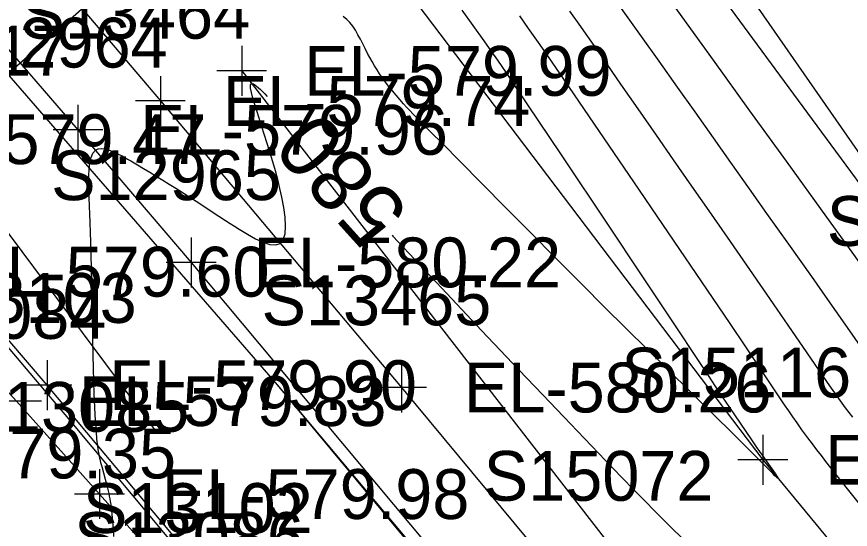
# Model space of a CAD drawing. Extents: x 1729869 to 1735532, y 648588 to 653771.
# Drawn here: x 1731311 to 1731377.9, y 651929.3 to 651970.4 of the extents above; entities that cross this region are included whole.
import ezdxf

# ---------------------------------------------------------------- set-up
doc = ezdxf.new("R2010")
doc.units = 0
for name, color, linetype in [('SURVEY - CENTERLINE - Preliminary', 7, 'Continuous'), ('SURVEY - CENTERLINE - Preliminary Text', 7, 'Continuous'), ('SURVEY - CONTOURS - Index with Text', 7, 'Continuous'), ('SURVEY - CONTOURS - Intermediate with optional Text', 7, 'Continuous'), ('SURVEY - DRAINAGE - Area Shapes', 7, 'Continuous'), ('SURVEY - DRAINAGE - Area Shapes Text', 7, 'Continuous'), ('SURVEY - DRAINAGE - Storm Sewer', 7, 'Continuous'), ('SURVEY - DTM - Breaklines', 7, 'Continuous'), ('SURVEY - DTM - Breaklines - Points - Elevations', 7, 'Continuous'), ('SURVEY - DTM - Breaklines - Points - Locators', 7, 'Continuous'), ('SURVEY - DTM - Breaklines - Points - Numbers', 7, 'Continuous'), ('SURVEY - TRANSPORTATION - Features', 7, 'Continuous'), ('SURVEY - TRANSPORTATION - Features - Points - Elevations', 7, 'Continuous'), ('SURVEY - TRANSPORTATION - Features - Points - Locators', 7, 'Continuous'), ('SURVEY - TRANSPORTATION - Features - Points - Numbers', 7, 'Continuous'), ('SURVEY - TRANSPORTATION - Roads', 7, 'Continuous'), ('SURVEY - TRANSPORTATION - Roads - Points - Elevations', 7, 'Continuous'), ('SURVEY - TRANSPORTATION - Roads - Points - Locators', 7, 'Continuous'), ('SURVEY - TRANSPORTATION - Roads - Points - Numbers', 7, 'Continuous')]:
    doc.layers.add(name, color=color, linetype=linetype)

msp = doc.modelspace()

# ---------------------------------------------------------------- linework, layer by layer
at = {"layer": 'SURVEY - CENTERLINE - Preliminary'}
msp.add_arc((1729018.342, 650008.232), 3000, 36.727042, 45.05905, dxfattribs=at)
at = {"layer": 'SURVEY - CENTERLINE - Preliminary Text'}
msp.add_line((1731292.149, 651977.382), (1731322.049, 651937.307), dxfattribs=at)
at = {"layer": 'SURVEY - CONTOURS - Index with Text'}
for points in [[(1731380.111, 651929.457), (1731376.642, 651933.822), (1731375.945, 651934.71), (1731375.586, 651935.173), (1731375.226, 651935.643), (1731374.866, 651936.118), (1731374.509, 651936.598), (1731374.03, 651937.255), (1731373.635, 651937.81), (1731373.297, 651938.294), (1731372.964, 651938.777), (1731372.636, 651939.258), (1731371.837, 651940.445), (1731369.521, 651943.908), (1731368.269, 651945.767), (1731366.448, 651948.459), (1731363.328, 651953.05), (1731360.529, 651957.162), (1731357.382, 651961.775), (1731354.92, 651965.384), (1731353.341, 651967.686), (1731352.751, 651968.54), (1731352.098, 651969.474), (1731351.377, 651970.491)], [(1731318.822, 651928.685), (1731318.786, 651929.299), (1731318.742, 651929.895), (1731318.69, 651930.466), (1731318.627, 651931.001), (1731318.592, 651931.245), (1731318.555, 651931.48), (1731318.515, 651931.706), (1731318.473, 651931.924), (1731318.429, 651932.136), (1731318.384, 651932.341), (1731318.309, 651932.656), (1731318.231, 651932.96), (1731318.153, 651933.253), (1731317.868, 651934.266), (1731317.778, 651934.604), (1731317.736, 651934.777), (1731317.695, 651934.953), (1731317.656, 651935.136), (1731317.607, 651935.391), (1731317.562, 651935.667), (1731317.52, 651935.968), (1731317.46, 651936.503), (1731317.408, 651937.1), (1731317.362, 651937.742), (1731317.322, 651938.413), (1731317.287, 651939.094), (1731317.244, 651940.122), (1731317.209, 651941.139), (1731317.181, 651942.168), (1731317.156, 651943.275), (1731317.137, 651944.391), (1731317.108, 651946.414), (1731317.089, 651947.534), (1731317.063, 651948.72), (1731317.032, 651949.97), (1731316.989, 651951.51), (1731316.937, 651953.09), (1731316.908, 651953.881), (1731316.831, 651955.873), (1731316.818, 651956.265), (1731316.809, 651956.65), (1731316.804, 651957.028), (1731316.807, 651957.626), (1731316.833, 651958.184), (1731316.889, 651958.687), (1731316.985, 651959.117), (1731317.129, 651959.458), (1731317.33, 651959.693), (1731317.551, 651959.801), (1731317.814, 651959.831), (1731318.113, 651959.794), (1731318.442, 651959.7), (1731318.795, 651959.56), (1731319.167, 651959.385), (1731319.413, 651959.26), (1731319.664, 651959.125), (1731319.92, 651958.983), (1731320.181, 651958.834), (1731320.713, 651958.522), (1731321.204, 651958.228), (1731321.706, 651957.926), (1731322.216, 651957.615), (1731322.732, 651957.297), (1731323.254, 651956.972), (1731323.78, 651956.642), (1731324.742, 651956.032), (1731325.717, 651955.404), (1731326.709, 651954.756), (1731327.78, 651954.051), (1731328.142, 651953.816), (1731328.505, 651953.583), (1731328.869, 651953.353), (1731329.534, 651952.95), (1731330.181, 651952.591), (1731330.789, 651952.307), (1731331.337, 651952.128), (1731331.804, 651952.085), (1731332.167, 651952.208), (1731332.412, 651952.516), (1731332.548, 651952.988), (1731332.59, 651953.595), (1731332.552, 651954.308), (1731332.45, 651955.097), (1731332.297, 651955.932), (1731332.144, 651956.632), (1731331.97, 651957.338), (1731331.781, 651958.047), (1731331.579, 651958.753), (1731331.369, 651959.453), (1731331.154, 651960.141), (1731330.858, 651961.066), (1731330.304, 651962.776), (1731330.121, 651963.357), (1731329.966, 651963.882), (1731329.851, 651964.331), (1731329.788, 651964.687), (1731329.788, 651964.93), (1731329.864, 651965.042), (1731330.026, 651965.01), (1731330.265, 651964.845), (1731330.568, 651964.57), (1731330.922, 651964.208), (1731331.105, 651964.009)], [(1731341.14, 651952.862), (1731341.202, 651952.796), (1731345.531, 651948.188), (1731348.325, 651945.226), (1731351.32, 651942.065), (1731353.245, 651940.044), (1731355.455, 651937.729), (1731358.838, 651934.202), (1731360.492, 651932.489), (1731361.498, 651931.453), (1731362.162, 651930.778), (1731362.846, 651930.091), (1731363.623, 651929.322), (1731364.37, 651928.593), (1731366.233, 651926.781), (1731368.579, 651924.483), (1731369.772, 651923.306), (1731372.732, 651920.367), (1731376.212, 651916.89), (1731379.682, 651913.401)]]:
    msp.add_lwpolyline(points, dxfattribs=at)
at = {"layer": 'SURVEY - CONTOURS - Intermediate with optional Text'}
for points in [[(1731365.805, 651974.472), (1731372.599, 651965.214), (1731376.345, 651960.121), (1731380.322, 651954.717)], [(1731362.163, 651973.501), (1731365.09, 651969.444), (1731366.904, 651966.925), (1731369.829, 651962.867), (1731372.756, 651958.811), (1731376.003, 651954.315), (1731377.682, 651951.987), (1731379.261, 651949.793)], [(1731378.922, 651943.681), (1731377.672, 651945.464), (1731376.115, 651947.695), (1731374.812, 651949.543), (1731372.969, 651952.154), (1731371.221, 651954.621), (1731369.821, 651956.601), (1731368.335, 651958.699), (1731366.936, 651960.677), (1731365.449, 651962.776), (1731364.051, 651964.753), (1731362.563, 651966.853), (1731361.166, 651968.829), (1731359.022, 651971.849)], [(1731346.747, 651970.943), (1731348.497, 651968.481), (1731349.115, 651967.601), (1731349.585, 651966.923), (1731350.281, 651965.908), (1731350.975, 651964.885), (1731352.013, 651963.344), (1731354.654, 651959.401), (1731358.591, 651953.514), (1731360.973, 651949.94), (1731362.951, 651946.962), (1731366.494, 651941.605), (1731367.338, 651940.334), (1731368.217, 651939.023), (1731369.06, 651937.777), (1731369.524, 651937.099), (1731369.98, 651936.434), (1731370.421, 651935.797), (1731370.839, 651935.197), (1731371.341, 651934.487), (1731371.743, 651933.924), (1731371.9, 651933.7), (1731372.019, 651933.525), (1731372.093, 651933.406), (1731372.114, 651933.351), (1731372.078, 651933.362), (1731371.991, 651933.435), (1731371.857, 651933.562), (1731371.684, 651933.733), (1731370.854, 651934.577), (1731370.403, 651935.033), (1731369.414, 651936.023), (1731368.364, 651937.066), (1731367.033, 651938.379), (1731363.234, 651942.106), (1731361.547, 651943.768), (1731360.013, 651945.287), (1731358.082, 651947.207), (1731356.513, 651948.777), (1731354.244, 651951.055), (1731352.235, 651953.085), (1731350.22, 651955.127), (1731348.396, 651956.979), (1731346.535, 651958.858), (1731345.228, 651960.169), (1731344.229, 651961.169), (1731343.569, 651961.838), (1731343.058, 651962.362), (1731342.806, 651962.626), (1731342.555, 651962.891), (1731342.307, 651963.157), (1731342.06, 651963.426), (1731341.759, 651963.763), (1731341.462, 651964.104), (1731341.171, 651964.45), (1731340.888, 651964.802), (1731340.614, 651965.16), (1731340.351, 651965.523), (1731340.136, 651965.837), (1731339.929, 651966.155), (1731339.73, 651966.477), (1731339.539, 651966.804), (1731339.355, 651967.133), (1731339.177, 651967.466), (1731338.983, 651967.847), (1731338.792, 651968.227), (1731338.601, 651968.602), (1731338.404, 651968.968), (1731338.198, 651969.32), (1731337.978, 651969.653), (1731337.759, 651969.938), (1731337.512, 651970.196), (1731337.227, 651970.418)], [(1731378.102, 651938.261), (1731377.816, 651938.636), (1731377.532, 651939.013), (1731377.121, 651939.569), (1731376.799, 651940.017), (1731376.529, 651940.397), (1731376.262, 651940.778), (1731375.734, 651941.54), (1731374.434, 651943.437), (1731372.931, 651945.638), (1731372.039, 651946.934), (1731369.845, 651950.11), (1731368.044, 651952.705), (1731366.576, 651954.822), (1731365.2, 651956.804), (1731363.734, 651958.916), (1731362.353, 651960.902), (1731360.889, 651963.01), (1731359.505, 651965), (1731358.044, 651967.104), (1731356.145, 651969.826), (1731355.41, 651970.87)]]:
    msp.add_lwpolyline(points, dxfattribs=at)
at = {"layer": 'SURVEY - DRAINAGE - Area Shapes'}
msp.add_lwpolyline([(1731447.67, 651794.75), (1731494.62, 651848.132), (1731494.044, 651850.166), (1731316.797, 652088.672), (1731252.279, 652032.718), (1731331.927, 651940.868), (1731377.361, 651886.729)], close=True, dxfattribs=at)
at = {"layer": 'SURVEY - DRAINAGE - Area Shapes Text'}
msp.add_lwpolyline([(1731252.279, 652032.718), (1731252.279, 652032.718), (1731331.927, 651940.868), (1731382.756, 651879.672), (1731447.67, 651794.75), (1731482.093, 651747.619), (1731463.009, 651708.574), (1731417.334, 651769.604), (1731372.727, 651826.43), (1731331.142, 651879.707), (1731270.184, 651948.802), (1731219.221, 652002.428), (1731149.8, 652071.308), (1731071.45, 652144.137), (1731094.843, 652173.647), (1731097.142, 652171.409), (1731179.777, 652109.245)], close=True, dxfattribs=at)
at = {"layer": 'SURVEY - DRAINAGE - Storm Sewer'}
msp.add_line((1731282.549, 651941.674), (1731329.545, 651982.643), dxfattribs=at)
at = {"layer": 'SURVEY - DTM - Breaklines'}
for points in [[(1731173.177, 652162.133), (1731185.96, 652157.822), (1731193.021, 652156.379), (1731200.301, 652157.188), (1731222.402, 652143.758), (1731259.134, 652109.719), (1731287.468, 652067.609), (1731323.876, 652033.257), (1731358.72, 651988.1), (1731387.259, 651947.011), (1731417.761, 651907.382), (1731444.904, 651865.257), (1731475.096, 651825.397), (1731506.912, 651797.592), (1731507.786, 651795.548)], [(1731334.173, 651982.596), (1731340.694, 651974.7), (1731370.886, 651934.84), (1731402.73, 651896.208), (1731431.321, 651855.159), (1731462.856, 651816.298), (1731496.995, 651790.22), (1731518.354, 651743.794), (1731543.329, 651700.057), (1731571.518, 651658.721), (1731573.975, 651653.989)], [(1731329.074, 651966.061), (1731359.729, 651926.546), (1731391.78, 651888.069), (1731423.005, 651848.978), (1731455.159, 651810.576), (1731479.951, 651777.549), (1731506.268, 651734.811), (1731535.375, 651694.144), (1731562.198, 651652.748), (1731588.043, 651609.921), (1731613.605, 651566.913), (1731639.146, 651523.891), (1731667.1, 651482.416), (1731693.639, 651440.035), (1731719.242, 651397.052), (1731747.215, 651355.589), (1731769.127, 651321.344), (1731788.96, 651288.223), (1731795.994, 651292.731)]]:
    msp.add_lwpolyline(points, dxfattribs=at)
at = {"layer": 'SURVEY - DTM - Breaklines - Points - Locators'}
for p, q in [((1731329.074, 651968.061), (1731329.074, 651964.061)), ((1731331.074, 651966.061), (1731327.074, 651966.061)), ((1731370.886, 651936.84), (1731370.886, 651932.84)), ((1731372.886, 651934.84), (1731368.886, 651934.84))]:
    msp.add_line(p, q, dxfattribs=at)
at = {"layer": 'SURVEY - TRANSPORTATION - Features'}
msp.add_lwpolyline([(1731258.402, 652039.18), (1731278.681, 652016.879), (1731284.056, 652009.864), (1731303.088, 651986.573), (1731322.547, 651963.645), (1731341.9, 651940.638), (1731361.109, 651917.48), (1731380.078, 651894.112), (1731398.716, 651870.573), (1731417.161, 651846.862), (1731435.465, 651822.971), (1731453.412, 651798.904), (1731471.112, 651774.585), (1731488.583, 651750.084), (1731505.82, 651725.418)], dxfattribs=at)
at = {"layer": 'SURVEY - TRANSPORTATION - Features - Points - Locators'}
for p, q in [((1731322.547, 651965.645), (1731322.547, 651961.645)), ((1731324.547, 651963.645), (1731320.547, 651963.645)), ((1731341.9, 651942.638), (1731341.9, 651938.638)), ((1731343.9, 651940.638), (1731339.9, 651940.638))]:
    msp.add_line(p, q, dxfattribs=at)
at = {"layer": 'SURVEY - TRANSPORTATION - Roads'}
for points in [[(1731269.804, 652013.975), (1731291.041, 651990.04), (1731301.561, 651977.986), (1731315.932, 651961.331), (1731325.019, 651950.684), (1731350.665, 651919.992), (1731374.621, 651890.497), (1731391.943, 651868.499), (1731406.718, 651849.586), (1731426.267, 651824.251), (1731439.451, 651806.638), (1731451.385, 651790.587), (1731473.705, 651759.831), (1731495.592, 651728.764)], [(1731389.825, 651846.468), (1731363.537, 651880.004), (1731354.147, 651891.444), (1731351.684, 651894.595), (1731349.211, 651897.739), (1731327.573, 651923.962), (1731313.451, 651940.828), (1731296.544, 651960.578), (1731283.394, 651975.645), (1731259.51, 652002.579)], [(1731269.179, 651985.304), (1731285.472, 651967.686), (1731301.624, 651949.938), (1731311.008, 651939.55), (1731317.661, 651932.085), (1731326.973, 651921.632), (1731337.476, 651909.563), (1731342.707, 651903.512), (1731346.624, 651898.967), (1731350.515, 651894.4), (1731358.298, 651885.268), (1731364.785, 651877.657)]]:
    msp.add_lwpolyline(points, dxfattribs=at)
at = {"layer": 'SURVEY - TRANSPORTATION - Roads - Points - Locators'}
for p, q in [((1731315.932, 651963.331), (1731315.932, 651959.331)), ((1731317.932, 651961.331), (1731313.932, 651961.331)), ((1731325.019, 651952.684), (1731325.019, 651948.684)), ((1731327.019, 651950.684), (1731323.019, 651950.684)), ((1731313.451, 651942.828), (1731313.451, 651938.828)), ((1731315.451, 651940.828), (1731311.451, 651940.828)), ((1731313.008, 651939.55), (1731309.008, 651939.55)), ((1731317.661, 651934.085), (1731317.661, 651930.085)), ((1731319.661, 651932.085), (1731315.661, 651932.085))]:
    msp.add_line(p, q, dxfattribs=at)

# ---------------------------------------------------------------- texts
at = {"layer": 'SURVEY - CONTOURS - Index with Text'}
msp.add_text('580', height=5, rotation=131.99508, dxfattribs=at).set_placement((1731342.639, 651954.794))
at = {"layer": 'SURVEY - DTM - Breaklines - Points - Elevations'}
for s, p in [('EL-579.99', (1731334.074, 651964.061)), ('EL-578.98', (1731375.886, 651932.84))]:
    msp.add_text(s, height=4, dxfattribs=at).set_placement(p)
at = {"layer": 'SURVEY - DTM - Breaklines - Points - Numbers'}
for s, p in [('S15142', (1731376.019, 651952.011)), ('S15116', (1731359.536, 651939.84)), ('S15072', (1731348.489, 651931.546))]:
    msp.add_text(s, height=4, dxfattribs=at).set_placement(p)
at = {"layer": 'SURVEY - TRANSPORTATION - Features - Points - Elevations'}
for s, p in [('EL-579.74', (1731327.547, 651961.645)), ('EL-580.26', (1731346.9, 651938.638))]:
    msp.add_text(s, height=4, dxfattribs=at).set_placement(p)
at = {"layer": 'SURVEY - TRANSPORTATION - Features - Points - Numbers'}
for s, p in [('S13464', (1731311.307, 651968.645)), ('S13465', (1731330.66, 651945.638))]:
    msp.add_text(s, height=4, dxfattribs=at).set_placement(p)
at = {"layer": 'SURVEY - TRANSPORTATION - Roads - Points - Elevations'}
for s, p in [('EL-579.17', (1731290.472, 651965.686)), ('EL-579.96', (1731320.932, 651959.331)), ('EL-579.47', (1731301.544, 651958.578)), ('EL-580.22', (1731330.019, 651948.684)), ('EL-579.60', (1731306.624, 651947.938)), ('EL-579.90', (1731318.451, 651938.828)), ('EL-579.83', (1731316.008, 651937.55)), ('EL-579.35', (1731299.121, 651933.34)), ('EL-579.98', (1731322.661, 651930.085))]:
    msp.add_text(s, height=4, dxfattribs=at).set_placement(p)
at = {"layer": 'SURVEY - TRANSPORTATION - Roads - Points - Numbers'}
for s, p in [('S12964', (1731304.692, 651966.331)), ('S12965', (1731313.779, 651955.684)), ('S13103', (1731302.211, 651945.828)), ('S13084', (1731299.768, 651944.55)), ('S13085', (1731306.421, 651937.085)), ('S13102', (1731316.333, 651928.962)), ('S13086', (1731315.623, 651926.632))]:
    msp.add_text(s, height=4, dxfattribs=at).set_placement(p)

doc.saveas('drawing.dxf')
